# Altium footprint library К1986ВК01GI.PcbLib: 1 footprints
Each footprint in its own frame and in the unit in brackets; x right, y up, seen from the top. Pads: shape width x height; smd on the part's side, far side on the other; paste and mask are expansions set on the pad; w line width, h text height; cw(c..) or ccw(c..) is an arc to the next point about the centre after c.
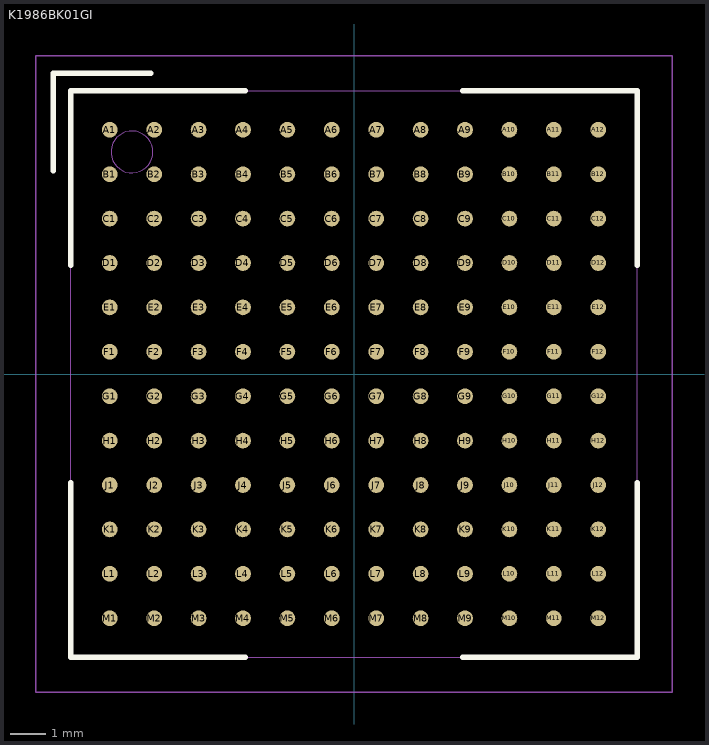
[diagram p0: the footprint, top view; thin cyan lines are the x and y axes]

## K1986BK01GI [mm] "Package Type - BGA144 16,2x16,2x2.5 (1,27)"
height 2.5
pads (144):
  round 0.45 smd mask+0.05: A1(-6.985,6.985) A2(-5.715,6.985) A3(-4.445,6.985) A4(-3.175,6.985) A5(-1.905,6.985) A6(-0.635,6.985) A7(0.635,6.985) A8(1.905,6.985) A9(3.175,6.985) A10(4.445,6.985) A11(5.715,6.985) A12(6.985,6.985) B1(-6.985,5.715) B2(-5.715,5.715) B3(-4.445,5.715) B4(-3.175,5.715) B5(-1.905,5.715) B6(-0.635,5.715) B7(0.635,5.715) B8(1.905,5.715) B9(3.175,5.715) B10(4.445,5.715) B11(5.715,5.715) B12(6.985,5.715) C1(-6.985,4.445) C2(-5.715,4.445) C3(-4.445,4.445) C4(-3.175,4.445) C5(-1.905,4.445) C6(-0.635,4.445) C7(0.635,4.445) C8(1.905,4.445) C9(3.175,4.445) C10(4.445,4.445) C11(5.715,4.445) C12(6.985,4.445) D1(-6.985,3.175) D2(-5.715,3.175) D3(-4.445,3.175) D4(-3.175,3.175) D5(-1.905,3.175) D6(-0.635,3.175) D7(0.635,3.175) D8(1.905,3.175) D9(3.175,3.175) D10(4.445,3.175) D11(5.715,3.175) D12(6.985,3.175) E1(-6.985,1.905) E2(-5.715,1.905) E3(-4.445,1.905) E4(-3.175,1.905) E5(-1.905,1.905) E6(-0.635,1.905) E7(0.635,1.905) E8(1.905,1.905) E9(3.175,1.905) E10(4.445,1.905) E11(5.715,1.905) E12(6.985,1.905) F1(-6.985,0.635) F2(-5.715,0.635) F3(-4.445,0.635) F4(-3.175,0.635) F5(-1.905,0.635) F6(-0.635,0.635) F7(0.635,0.635) F8(1.905,0.635) F9(3.175,0.635) F10(4.445,0.635) F11(5.715,0.635) F12(6.985,0.635) G1(-6.985,-0.635) G2(-5.715,-0.635) G3(-4.445,-0.635) G4(-3.175,-0.635) G5(-1.905,-0.635) G6(-0.635,-0.635) G7(0.635,-0.635) G8(1.905,-0.635) G9(3.175,-0.635) G10(4.445,-0.635) G11(5.715,-0.635) G12(6.985,-0.635) H1(-6.985,-1.905) H2(-5.715,-1.905) H3(-4.445,-1.905) H4(-3.175,-1.905) H5(-1.905,-1.905) H6(-0.635,-1.905) H7(0.635,-1.905) H8(1.905,-1.905) H9(3.175,-1.905) H10(4.445,-1.905) H11(5.715,-1.905) H12(6.985,-1.905) J1(-6.985,-3.175) J2(-5.715,-3.175) J3(-4.445,-3.175) J4(-3.175,-3.175) J5(-1.905,-3.175) J6(-0.635,-3.175) J7(0.635,-3.175) J8(1.905,-3.175) J9(3.175,-3.175) J10(4.445,-3.175) J11(5.715,-3.175) J12(6.985,-3.175) K1(-6.985,-4.445) K2(-5.715,-4.445) K3(-4.445,-4.445) K4(-3.175,-4.445) K5(-1.905,-4.445) K6(-0.635,-4.445) K7(0.635,-4.445) K8(1.905,-4.445) K9(3.175,-4.445) K10(4.445,-4.445) K11(5.715,-4.445) K12(6.985,-4.445) L1(-6.985,-5.715) L2(-5.715,-5.715) L3(-4.445,-5.715) L4(-3.175,-5.715) L5(-1.905,-5.715) L6(-0.635,-5.715) L7(0.635,-5.715) L8(1.905,-5.715) L9(3.175,-5.715) L10(4.445,-5.715) L11(5.715,-5.715) L12(6.985,-5.715) M1(-6.985,-6.985) M2(-5.715,-6.985) M3(-4.445,-6.985) M4(-3.175,-6.985) M5(-1.905,-6.985) M6(-0.635,-6.985) M7(0.635,-6.985) M8(1.905,-6.985) M9(3.175,-6.985) M10(4.445,-6.985) M11(5.715,-6.985) M12(6.985,-6.985)
Top Overlay:
  lines w0.15: -8.6,5.815 -8.6,8.6 -5.815,8.6 ; -8.1,-3.1 -8.1,-8.1 -3.1,-8.1 ; -8.1,3.1 -8.1,8.1 -3.1,8.1 ; 3.1,-8.1 8.1,-8.1 8.1,-3.1 ; 3.1,8.1 8.1,8.1 8.1,3.1
Top Assembly:
  circle w0: c-6.35,6.35 r0.6
  lines w0: -8.1,-8.1 8.1,-8.1 8.1,8.1 -8.1,8.1 -8.1,-8.1
  text ".Designator" at -2.618,-0.355 h1.52
Top Courtyard:
  lines w0.05: -9.1,-9.1 9.1,-9.1 9.1,9.1 -9.1,9.1 -9.1,-9.1
3D body "BGA144C127P12X12_1620X1620X250_2.STEP": height 2.51, standoff 0, extent -8.1,-8.1 8.1,8.1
